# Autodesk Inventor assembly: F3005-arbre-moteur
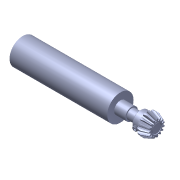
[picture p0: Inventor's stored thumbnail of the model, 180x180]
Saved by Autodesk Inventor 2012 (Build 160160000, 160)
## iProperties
Created: 2014-12
Part Number: F3005-arbre-moteur
Document SubType Name: Assembly
Designer: Bruno
Mass: 29.9389 g
Surface Area: 81.6686 cm^2
Volume: 29.9389 cm^3
Density: 1 g/cm^3
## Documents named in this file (4)
- F:\Systèmes\secateur-hydrogene-Pragma\Documentation\Dossier technique Infaco F3005\Solidworks\Composants importés\F3005-arbre-moteur.iam
- F:\Systèmes\secateur-hydrogene-Pragma\Documentation\Dossier technique Infaco F3005\Solidworks\Composants importés\F3005\Pignon 15dts.ipt
- F:\Systèmes\secateur-hydrogene-Pragma\Documentation\Dossier technique Infaco F3005\Solidworks\Composants importés\F3005\Vis pignon 15dts.ipt
- F:\Systèmes\secateur-hydrogene-Pragma\Documentation\Dossier technique Infaco F3005\Solidworks\Composants importés\F3005\Bobine moteur.ipt
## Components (3 placed, 3 different names)
1. Pignon 15dts:1 — Placage:1, Affleurement:1, Affleurement:2
2. Vis pignon 15dts:1 — Placage:2
3. Bobine moteur:1 — Placage:1, Placage:2, Affleurement:1
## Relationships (4: Mate 2, Flush 2)
- Placage:1 [Mate]: Pignon 15dts:1 ↔ Bobine moteur:1
- Placage:2 [Mate]: Vis pignon 15dts:1 ↔ Bobine moteur:1
- Affleurement:1 [Flush]: Pignon 15dts:1 ↔ Bobine moteur:1
- Affleurement:2 [Flush]: Pignon 15dts:1
